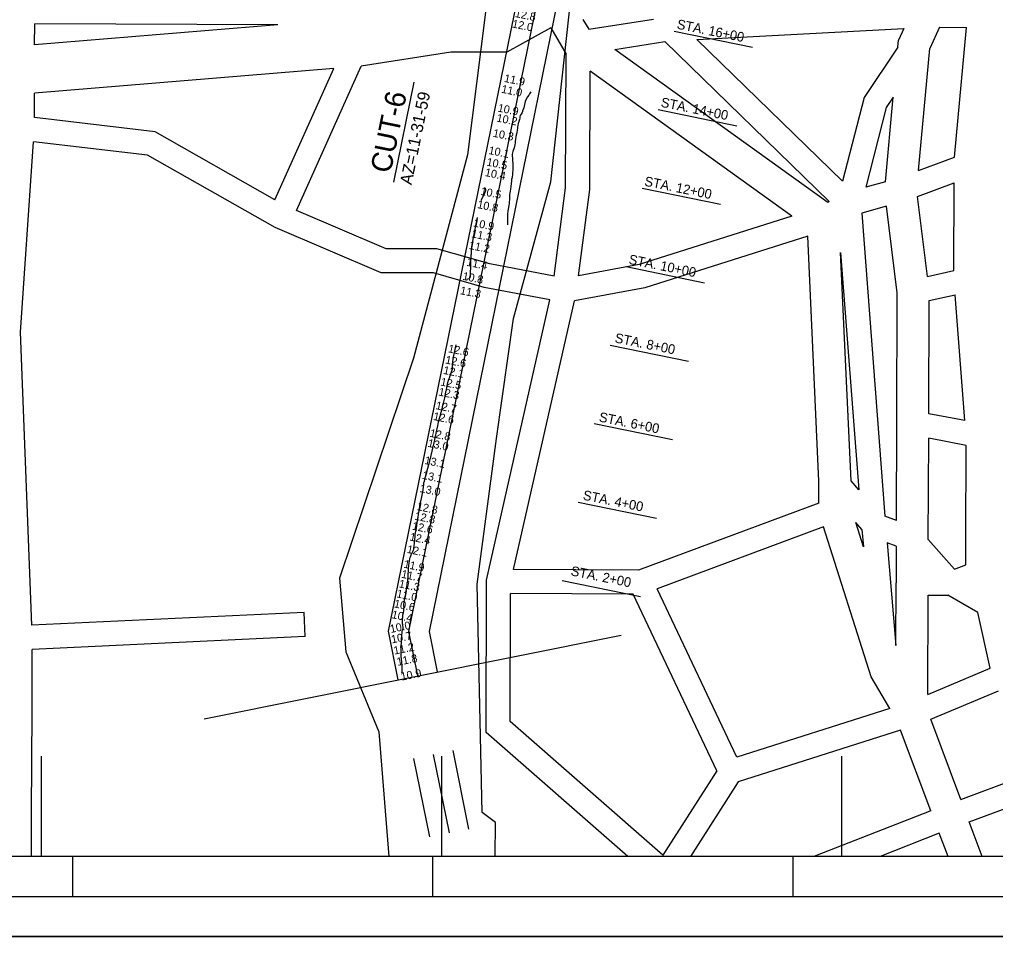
# Model space of a CAD drawing. Extents: x 501128 to 509328, y 1314906 to 1320706.
# Drawn here: x 504945 to 507384, y 1314906 to 1317196 of the extents above; entities that cross this region are included whole.
import ezdxf

# ---------------------------------------------------------------- set-up
doc = ezdxf.new("R2010")
doc.units = 0
for name, color, linetype in [('G-ANNO-TTLB', 7, 'Continuous'), ('Level 1', 7, 'Continuous'), ('Level 14', 7, 'Continuous'), ('Level 2', 7, 'Continuous'), ('Level 23', 7, 'Continuous'), ('Level 32', 7, 'Continuous'), ('Level 49', 7, 'Continuous'), ('Level 5', 7, 'Continuous'), ('Level 50', 7, 'Continuous'), ('Level 51', 7, 'Continuous'), ('Level 56', 7, 'Continuous'), ('Level 58', 7, 'Continuous'), ('Level 6', 7, 'Continuous')]:
    doc.layers.add(name, color=color, linetype=linetype)

msp = doc.modelspace()

# ---------------------------------------------------------------- linework, layer by layer
at = {"layer": 'G-ANNO-TTLB'}
for p, q in [((509128.1, 1315106.3), (501478.1, 1315106.3)), ((505078.1, 1315006.3), (505078.1, 1315106.3)), ((505978.1, 1315006.3), (505978.1, 1315106.3)), ((506878.1, 1315006.3), (506878.1, 1315106.3)), ((501228.1, 1315006.3), (509228.1, 1315006.3))]:
    msp.add_line(p, q, dxfattribs=at)
for points in [[(501128.1, 1314906.3), (509328.1, 1314906.3), (509328.1, 1320706.3), (501128.1, 1320706.3)], [(501128.1, 1314906.3), (509328.1, 1314906.3), (509328.1, 1320706.3), (501128.1, 1320706.3)], [(501128.1, 1320706.3), (509328.1, 1320706.3), (509328.1, 1314906.3), (501128.1, 1314906.3)]]:
    msp.add_lwpolyline(points, close=True, dxfattribs=at)
at = {"layer": 'Level 1'}
for points in [[(506222.2, 1317015.1), (506219.3, 1317010.5), (506217.3, 1317007.1), (506214.6, 1317002.7), (506211.3, 1316997.1), (506208.6, 1316990.8), (506206.4, 1316983.7), (506204.7, 1316975.7), (506202.8, 1316969.1), (506200.6, 1316963.8), (506198.1, 1316959.8), (506196.3, 1316956), (506195.3, 1316952.7), (506194.9, 1316949.6), (506194.1, 1316945.8), (506192.9, 1316941.3), (506191.2, 1316936), (506190, 1316931.5), (506189.4, 1316927.7), (506189.3, 1316924.7), (506188.6, 1316919.7), (506187.3, 1316912.7), (506185.4, 1316903.9), (506184.1, 1316896.8), (506183.5, 1316891.5), (506183.5, 1316888), (506182.6, 1316882.7), (506180.7, 1316875.4), (506177.9, 1316866.4), (506176.3, 1316859.2), (506175.8, 1316853.8), (506176.4, 1316850.4), (506176.9, 1316846.5), (506177.2, 1316842.3), (506177.4, 1316837.6), (506177.5, 1316833), (506177.7, 1316828.5), (506177.8, 1316824), (506177.7, 1316819.1), (506177.2, 1316813.6), (506176.5, 1316807.6), (506175.9, 1316802.7), (506175.2, 1316798.9), (506174.6, 1316796.2), (506174, 1316791.8), (506173.4, 1316786), (506172.6, 1316778.5), (506171.9, 1316772.2), (506171.1, 1316767), (506170.4, 1316762.9), (506169.7, 1316758), (506169.2, 1316752.3), (506168.9, 1316745.7), (506168.6, 1316740.7), (506168.4, 1316737.4), (506168.3, 1316735.8), (506167.8, 1316732), (506166.8, 1316726.1), (506165.3, 1316718.1), (506164.4, 1316709.8), (506164, 1316701.1), (506164.1, 1316683.1)], [(506098.4, 1316744.4), (506105.7, 1316759.3), (506108.3, 1316764.9), (506109.8, 1316768.6), (506110.4, 1316770.6), (506110.3, 1316772.2), (506109.6, 1316773.7), (506106.8, 1316776.2)], [(506088.3, 1316701.1), (506078.3, 1316651.6), (506075, 1316633.1), (506073.3, 1316620.8), (506073.3, 1316614.8), (506073.2, 1316610.3), (506073, 1316607.2), (506072.6, 1316605.7), (506072.4, 1316602.1), (506072.2, 1316596.5), (506072.1, 1316588.9), (506071.9, 1316581.6), (506071.7, 1316574.4), (506071.4, 1316567.4), (506071.2, 1316561.6), (506071, 1316556.9), (506070.9, 1316553.3), (506069.8, 1316550.6), (506067.7, 1316548.7), (506061.8, 1316546.7)], [(506035.6, 1316383.9), (506031.1, 1316364.3), (506029.4, 1316357.1), (506028.4, 1316352.6), (506027.9, 1316350.8), (506027.5, 1316347.2), (506027, 1316342), (506026.5, 1316335), (506026.2, 1316329.4), (506025.9, 1316325.1), (506025.8, 1316322.2), (506024.8, 1316318), (506023, 1316312.5), (506020.4, 1316305.7), (506018.4, 1316300.6), (506017.1, 1316297), (506016.3, 1316295), (506015.2, 1316291), (506013.8, 1316285), (506012, 1316276.9), (506010.8, 1316271.1), (506010, 1316267.5), (506009.8, 1316266), (506008.7, 1316260.7), (506006.6, 1316251.4), (506003.6, 1316238.2), (506001.4, 1316228.7), (506000, 1316223), (505999.4, 1316221.1), (505998.9, 1316219.3), (505998.5, 1316217.7), (505998.2, 1316216.2), (505997.3, 1316212.7), (505995.7, 1316207.2), (505993.5, 1316199.7), (505991.3, 1316191.1), (505989.1, 1316181.4), (505986.8, 1316170.5), (505985.1, 1316162.6), (505984, 1316157.7), (505983.5, 1316155.7), (505982.7, 1316152), (505981.5, 1316146.5), (505980.1, 1316139.3), (505979, 1316134.2), (505978.3, 1316131), (505978, 1316129.9), (505977, 1316125.6), (505975.2, 1316118), (505972.6, 1316107.2), (505970.7, 1316099.6), (505969.7, 1316095.2), (505969.4, 1316093.9), (505968.4, 1316090), (505966.7, 1316083.7), (505964.3, 1316074.8), (505962.7, 1316068.6), (505961.8, 1316065.1), (505961.6, 1316064.2), (505960.8, 1316061.1), (505959.3, 1316055.6), (505957.2, 1316047.9), (505955.7, 1316042.5), (505954.9, 1316039.6), (505954.8, 1316039)], [(505954.8, 1316039), (505954.5, 1316035.7), (505953.8, 1316029.6), (505952.8, 1316020.6), (505951.4, 1316012), (505949.6, 1316003.8), (505947.4, 1315995.9), (505945.9, 1315990.4), (505945.2, 1315987.3), (505945.1, 1315986.6), (505944.4, 1315981.9), (505943.2, 1315973.4), (505941.4, 1315961), (505940.1, 1315952.4), (505939.3, 1315947.8), (505939.1, 1315947), (505939, 1315946.2), (505938.8, 1315945.4), (505938.7, 1315944.5), (505938, 1315940.3), (505936.8, 1315932.6), (505935, 1315921.6), (505933.7, 1315913.8), (505933, 1315909.2), (505932.8, 1315907.8), (505932.4, 1315903.9), (505931.8, 1315897.4), (505930.9, 1315888.2), (505930.2, 1315881.3), (505929.7, 1315876.7), (505929.4, 1315874.2), (505928.2, 1315870.3), (505926, 1315865), (505922.9, 1315858.3), (505920.8, 1315853.3), (505919.6, 1315850.1), (505919.4, 1315848.6), (505918.9, 1315845.1), (505918.1, 1315839.6), (505917, 1315832.2), (505916.2, 1315825), (505915.8, 1315818.2), (505915.6, 1315811.6), (505915.4, 1315806.6), (505915.2, 1315803.1), (505914.9, 1315801.1), (505914.6, 1315799), (505914.4, 1315796.8), (505914.2, 1315794.4), (505913.8, 1315790.8), (505913.1, 1315785.9), (505912.1, 1315779.6), (505911.4, 1315774.6), (505910.9, 1315770.8), (505910.6, 1315768.1), (505909.8, 1315763.4), (505908.4, 1315756.7), (505906.5, 1315747.9), (505905.3, 1315740.7), (505904.7, 1315735.3), (505904.8, 1315731.4), (505904.9, 1315728.1), (505904.8, 1315725.2), (505904.5, 1315722.7), (505904.1, 1315719.1)], [(505904.1, 1315719.1), (505903.3, 1315714.3), (505902.2, 1315708.4), (505901.6, 1315703.1), (505901.2, 1315698.6), (505901.3, 1315694.8), (505901.3, 1315691.7), (505901.3, 1315689.2), (505901.3, 1315687.4), (505901.6, 1315685), (505902.2, 1315682), (505903, 1315678.5), (505903.2, 1315675.7), (505902.8, 1315673.5), (505901.7, 1315671.9), (505900.9, 1315670.2), (505900.5, 1315668.3), (505900.3, 1315666.3), (505900.1, 1315663.5), (505899.8, 1315660), (505899.3, 1315655.7), (505899, 1315651.8), (505898.7, 1315648.3), (505898.5, 1315645.2), (505898.4, 1315639.8), (505898.2, 1315632.2), (505897.9, 1315622.4), (505897.8, 1315615.3), (505897.7, 1315611.1), (505897.7, 1315609.6), (505898.1, 1315605.7), (505898.7, 1315599.4), (505899.7, 1315590.7), (505900.3, 1315583.2), (505900.5, 1315576.7), (505900.3, 1315571.4), (505900.1, 1315567.7), (505899.9, 1315565.7), (505899.6, 1315564.9)]]:
    msp.add_lwpolyline(points, dxfattribs=at)
at = {"layer": 'Level 14'}
for p, q in [((505590.2, 1317182.6), (504982.8, 1317132.3)), ((506272.3, 1317175.1), (506163, 1317114.1)), ((507281.4, 1316852.4), (507311.3, 1317176.1)), ((506022.9, 1317114.6), (505798.3, 1317079.3)), ((506163, 1317114.1), (506022.9, 1317114.6)), ((505730, 1317073.8), (504982.3, 1317011.9)), ((507279.7, 1316569), (507280.5, 1316788.1)), ((507306.9, 1316194.2), (507282.7, 1316508.3)), ((507309.4, 1315897.3), (507310.3, 1316132.5)), ((507309.2, 1315834.1), (507309.4, 1315897.3)), ((507370, 1315575.9), (507339.5, 1315715.6))]:
    msp.add_line(p, q, dxfattribs=at)
at = {"layer": 'Level 2'}
for p, q in [((505000, 1315106.3), (505000, 1315356.3)), ((506000, 1315106.3), (506000, 1315356.3)), ((507000, 1315106.3), (507000, 1315356.3))]:
    msp.add_line(p, q, dxfattribs=at)
at = {"layer": 'Level 23'}
for p, q in [((506352.7, 1317196.2), (506367.2, 1317171.5)), ((506272.3, 1317175.1), (506310.9, 1317109.3)), ((507154.2, 1317173.3), (507141.2, 1317144.2)), ((507243.3, 1317176.3), (507219.6, 1317123.5)), ((507139.6, 1317126.9), (507141.2, 1317144.2)), ((506964.4, 1316739.3), (506432.1, 1317121)), ((507191.4, 1316819), (507219.6, 1317123.5)), ((506874.7, 1316705.2), (506370.7, 1317066.5)), ((507108.4, 1316790.9), (507128, 1317002)), ((507213.6, 1316554.4), (507189, 1316754.1)), ((507138, 1316513.4), (507111.4, 1316729.5)), ((506942.5, 1316043.1), (506914.7, 1316654.9)), ((507022.6, 1316043.9), (506996.6, 1316614.1)), ((507136.8, 1316188.8), (507138, 1316513.4)), ((507216.9, 1316211.5), (507218, 1316493.9)), ((507135.9, 1315945), (507136.8, 1316188.8)), ((507215.7, 1315897.8), (507216.7, 1316150.4)), ((506942.3, 1315988.4), (506942.5, 1316043.1)), ((507053.6, 1315879.2), (507034.2, 1315939.9)), ((507073.1, 1315554.4), (506953.9, 1315928.7)), ((507135.6, 1315880.9), (507135.3, 1315788.9)), ((507134.7, 1315633.2), (507135.3, 1315788.9)), ((507214.2, 1315510.8), (507215.2, 1315758.6)), ((507119.4, 1315475.6), (507073.1, 1315554.4)), ((507296.9, 1315248.7), (507221.6, 1315448.9)), ((507222.1, 1315220.2), (507146.5, 1315421.3)), ((507350.5, 1315106.3), (507318, 1315192.5)), ((507265, 1315106.3), (507243.2, 1315164.1))]:
    msp.add_line(p, q, dxfattribs=at)
at = {"layer": 'Level 32'}
for p, q in [((504982.8, 1317132.3), (504983, 1317184.9)), ((505590.2, 1317182.6), (504983, 1317184.9)), ((506367.2, 1317171.5), (506528.8, 1317196.9)), ((506637.3, 1317146.2), (507154.2, 1317173.3)), ((507243.3, 1317176.3), (507311.3, 1317176.1)), ((506432.1, 1317121), (506557, 1317140.6)), ((506557, 1317140.6), (506967.7, 1316741.1)), ((506637.3, 1317146.2), (507001.3, 1316792.1)), ((506309.6, 1316775.5), (506310.9, 1317109.3)), ((505583, 1316746), (505730, 1317073.8)), ((505636.7, 1316719.2), (505798.3, 1317079.3)), ((506369.6, 1316771.5), (506370.7, 1317066.5)), ((504982.1, 1316950.9), (504982.3, 1317011.9)), ((504947.8, 1316414.9), (504979.8, 1316890.7)), ((507191.4, 1316819), (507281.4, 1316852.4)), ((507108.4, 1316790.9), (507059.5, 1316777.3)), ((507189, 1316754.1), (507280.5, 1316788.1)), ((506280.8, 1316554.6), (506309.6, 1316775.5)), ((506341.5, 1316556.1), (506369.6, 1316771.5)), ((506967.7, 1316741.1), (506964.4, 1316739.3)), ((505860.9, 1316623.5), (505636.7, 1316719.2)), ((507111.4, 1316729.5), (507049.2, 1316712.2)), ((507049.2, 1316712.2), (507107.4, 1315955.8)), ((505848.5, 1316563.6), (505583.5, 1316676.7)), ((505988.1, 1316623), (505860.9, 1316623.5)), ((506119.8, 1316585.4), (505988.1, 1316623)), ((506996.6, 1316614.1), (507042.2, 1316021.6)), ((506280.8, 1316554.6), (506119.8, 1316585.4)), ((507213.6, 1316554.4), (507279.7, 1316569)), ((505979.6, 1316563.1), (505848.5, 1316563.6)), ((506105.9, 1316527), (505979.6, 1316563.1)), ((506270.3, 1316495.5), (506105.9, 1316527)), ((506112.2, 1315796), (506270.3, 1316495.5)), ((507218, 1316493.9), (507282.7, 1316508.3)), ((506179.7, 1315822.5), (506331.3, 1316493.2)), ((504975.9, 1315683.2), (504947.8, 1316414.9)), ((507306.9, 1316194.2), (507216.9, 1316211.5)), ((507310.3, 1316132.5), (507216.7, 1316150.4)), ((507042.2, 1316021.6), (507022.6, 1316043.9)), ((506942.3, 1315988.4), (506492, 1315821.3)), ((507049.9, 1315922.1), (507034.2, 1315939.9)), ((507135.9, 1315945), (507107.4, 1315955.8)), ((506953.9, 1315928.7), (506538.4, 1315774.5)), ((507049.9, 1315922.1), (507053.6, 1315879.2)), ((507135.6, 1315880.9), (507112.9, 1315889.5)), ((507112.9, 1315889.5), (507134.7, 1315633.2)), ((507281, 1315823.6), (507215.7, 1315897.8)), ((506492, 1315821.3), (506179.7, 1315822.5)), ((507281, 1315823.6), (507309.2, 1315834.1)), ((506737.4, 1315354.3), (506538.4, 1315774.5)), ((506478.3, 1315761.4), (506172.1, 1315762.5)), ((506687.3, 1315320), (506478.3, 1315761.4)), ((507215.2, 1315758.6), (507264.2, 1315758.4)), ((507339.5, 1315715.6), (507264.2, 1315758.4)), ((505656.1, 1315715.4), (504975.9, 1315683.2)), ((505658.9, 1315655.4), (505656.1, 1315715.4)), ((505658.9, 1315655.4), (504977, 1315623.1)), ((504976.4, 1315469.9), (504977, 1315623.1)), ((507214.2, 1315510.8), (507370, 1315575.9)), ((507221.6, 1315448.9), (507390.8, 1315519.6)), ((507119.4, 1315475.6), (506737.4, 1315354.3)), ((504975.4, 1315215.4), (504976.4, 1315469.9)), ((507146.5, 1315421.3), (506740.9, 1315292.5)), ((506687.3, 1315320), (506552.6, 1315109.4)), ((507296.9, 1315248.7), (507490.8, 1315320.6)), ((506740.9, 1315292.5), (506621.8, 1315106.3)), ((507318, 1315192.5), (507510.6, 1315264)), ((504975, 1315106.3), (504975.4, 1315215.4)), ((507222.1, 1315220.2), (506929.8, 1315106.3)), ((507243.2, 1315164.1), (507095, 1315106.3))]:
    msp.add_line(p, q, dxfattribs=at)
for points in [[(507139.6, 1317126.9), (507055.2, 1317001.3), (507001.3, 1316792.1)], [(507128, 1317002), (507110.7, 1316976.3), (507059.5, 1316777.3)], [(505583, 1316746), (505284.2, 1316915.7), (504982.1, 1316950.9)], [(505583.5, 1316676.7), (505265.2, 1316857.5), (504979.8, 1316890.7)], [(506874.7, 1316705.2), (506492.9, 1316583.9), (506341.5, 1316556.1)], [(506914.7, 1316654.9), (506507.5, 1316525.6), (506331.3, 1316493.2)], [(506465, 1315106.3), (506110.8, 1315415.5), (506112.2, 1315796)], [(506552.6, 1315109.4), (506170.9, 1315442.7), (506172.1, 1315762.5)]]:
    msp.add_lwpolyline(points, dxfattribs=at)
at = {"layer": 'Level 5'}
for points in [[(502988.5, 1320506.3), (503056.9, 1320142.4), (503189.4, 1319858.7), (503438.4, 1319516.2), (504086.3, 1318789.2), (504252.7, 1318680.4), (504544, 1318562.8), (505451.9, 1318368.4), (505926.4, 1318183.7), (506109.2, 1317999.8), (506132.4, 1317399.6), (506064.1, 1316858.1), (505929.2, 1316350.1), (505744.2, 1315800.6), (505760.3, 1315617.2), (505843.1, 1315416.9), (505867.7, 1315106.3)], [(506133.9, 1315106.3), (506134.1, 1315191), (506100.8, 1315216.1), (506088.6, 1315786), (506137, 1316149.5), (506179.5, 1316449.4), (506272.3, 1316790.8), (506340.8, 1317415.6), (506508.7, 1317823.5), (506567.6, 1317998.4), (506518.7, 1318373.6), (506369, 1318507.4), (506052.8, 1318658.3), (505377.9, 1318693.7), (504936.3, 1318761.6), (504770.1, 1318912.2), (504728.7, 1319020.6), (504387.5, 1319163.3), (503822.6, 1319798.4), (503531.7, 1320041), (503232.9, 1320458.6), (503215.7, 1320506.3)]]:
    msp.add_lwpolyline(points, dxfattribs=at)
at = {"layer": 'Level 50'}
for p, q in [((505969.1, 1315668), (506442, 1317985.8)), ((505867, 1315668.2), (506291.3, 1317747.1)), ((505891.3, 1315547.1), (505867, 1315668.2)), ((505989.4, 1315566.8), (505969.1, 1315668))]:
    msp.add_line(p, q, dxfattribs=at)
at = {"layer": 'Level 51'}
msp.add_line((505880.2, 1316789.9), (505931.2, 1317039.8), dxfattribs=at)
at = {"layer": 'Level 56'}
for p, q in [((506776.8, 1317125.8), (506580.9, 1317165.8)), ((506736.9, 1316929.9), (506540.9, 1316969.9)), ((506696.9, 1316733.9), (506500.9, 1316773.9)), ((506656.9, 1316537.9), (506460.9, 1316577.9)), ((506616.9, 1316342), (506420.9, 1316382)), ((506576.9, 1316146), (506381, 1316186)), ((506536.9, 1315950.1), (506341, 1315990)), ((506496.9, 1315754.1), (506301, 1315794.1)), ((505969.9, 1315154.9), (505930.6, 1315351)), ((506019, 1315164.7), (505979.6, 1315360.8)), ((506068, 1315174.6), (506028.7, 1315370.7))]:
    msp.add_line(p, q, dxfattribs=at)
at = {"layer": 'Level 58'}
msp.add_line((505406.1, 1315449.9), (506448.3, 1315658.8), dxfattribs=at)
at = {"layer": 'Level 6'}
for p, q in [((505918.1, 1315668.1), (506390.2, 1317982.1)), ((505940.3, 1315556.9), (505918.1, 1315668.1))]:
    msp.add_line(p, q, dxfattribs=at)

# ---------------------------------------------------------------- texts
at = {"layer": 'Level 49'}
for s, rotation, p in [('12.8 ', 348.4669, (506181.7, 1317202.3)), ('12.0 ', 348.4669, (506174.7, 1317176.3)), ('11.9 ', 348.4669, (506154.7, 1317040.3)), ('11.0 ', 348.4669, (506147.7, 1317013.3)), ('10.9 ', 348.4669, (506138.7, 1316966.3)), ('10.2 ', 348.4669, (506135.7, 1316941.3)), ('10.3 ', 348.4669, (506126.7, 1316903.3)), ('10.1 ', 348.4669, (506115.7, 1316860.3)), ('10.5 ', 348.4669, (506110.7, 1316831.3)), ('10.4 ', 348.4669, (506106.7, 1316805.3)), ('10.5 ', 348.4669, (506095.7, 1316758.3)), ('10.8 ', 348.4669, (506087.7, 1316725.3)), ('10.9 ', 348.4669, (506077.7, 1316679.3)), ('11.3 ', 348.4669, (506072.7, 1316652.3)), ('11.2 ', 348.4669, (506066.7, 1316623.3)), ('11.4 ', 348.4669, (506060.7, 1316581.3)), ('10.8 ', 348.4669, (506050.7, 1316546.3)), ('11.3 ', 348.4669, (506044.7, 1316510.3)), ('12.6 ', 348.4669, (506014.7, 1316365.3)), ('12.6 ', 348.4669, (506007.7, 1316337.3)), ('12.1 ', 348.4669, (506002.7, 1316311.3)), ('12.5 ', 348.4669, (505995.7, 1316282.3)), ('12.3 ', 348.4669, (505990.7, 1316257.3)), ('12.7 ', 348.4669, (505983.7, 1316223.3)), ('12.6 ', 348.4669, (505977.7, 1316196.3)), ('12.8 ', 348.4669, (505968.7, 1316154.3)), ('13.0 ', 348.4669, (505963.7, 1316129.3)), ('13.1 ', 348.4669, (505955.7, 1316086.3)), ('13.1 ', 348.4669, (505949.7, 1316049.3)), ('13.0 ', 348.4669, (505943.7, 1316016.3)), ('12.8 ', 348.4669, (505936.7, 1315971.3)), ('12.8 ', 348.4669, (505930.7, 1315947.3)), ('12.6 ', 348.4669, (505924.7, 1315922.3)), ('12.4 ', 348.4669, (505918.7, 1315895.3)), ('12.1 ', 348.4669, (505911.7, 1315864.3)), ('11.9 ', 348.4669, (505903.7, 1315827.3)), ('11.7 ', 348.4669, (505897.7, 1315802.3)), ('11.3 ', 348.4669, (505891.7, 1315778.3)), ('11.0 ', 348.4669, (505885.7, 1315753.3)), ('10.6 ', 348.4669, (505879.7, 1315728.3)), ('10.4 ', 348.4669, (505873.7, 1315701.3)), ('10.0 ', 11.3343, (505872.7, 1315664)), ('10.7 ', 11.3343, (505875.7, 1315638)), ('11.2 ', 11.3343, (505881.7, 1315610)), ('11.8 ', 11.3343, (505889.7, 1315582)), ('10.9 ', 11.3343, (505899.7, 1315545))]:
    msp.add_text(s, height=20, rotation=rotation, dxfattribs=at).set_placement(p)
at = {"layer": 'Level 51'}
for s, height, p in [('CUT-6', 52, (505872.1, 1316810)), ('AZ=11-31-59', 30, (505924.5, 1316781.5))]:
    msp.add_text(s, height=height, rotation=78.4669, dxfattribs=at).set_placement(p)
at = {"layer": 'Level 56'}
for s, p in [('STA. 16+00', (506586, 1317173.2)), ('STA. 14+00', (506546, 1316978.2)), ('STA. 12+00', (506504.9, 1316781.1)), ('STA. 10+00', (506465.7, 1316586)), ('STA. 8+00', (506431, 1316389.8)), ('STA. 6+00', (506391.4, 1316192.4)), ('STA. 4+00', (506351.4, 1315997.3)), ('STA. 2+00', (506321, 1315808.1))]:
    msp.add_text(s, height=24, rotation=348.542, dxfattribs=at).set_placement(p)

doc.saveas('drawing.dxf')
